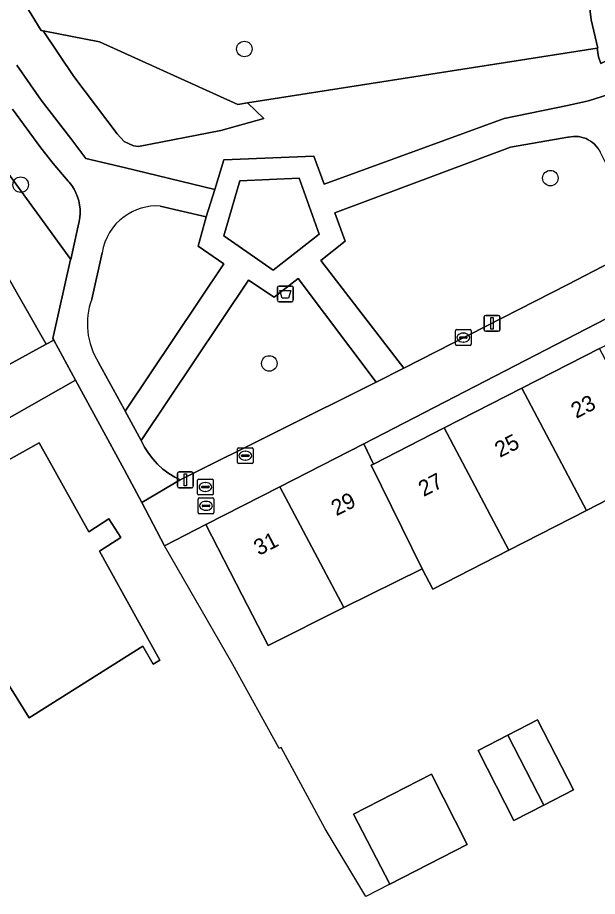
# Model space of a CAD drawing. Extents: x 160377 to 161131, y 383938 to 384853.
# Drawn here: x 160993.3 to 161029.8, y 384084.7 to 384140 of the extents above; entities that cross this region are included whole.
import ezdxf

# ---------------------------------------------------------------- set-up
doc = ezdxf.new("R2010")
doc.units = 0
for name, color, linetype in [('IMGEO_Afvalbak', 7, 'Continuous'), ('IMGEO_Boom', 7, 'Continuous'), ('IMGEO_Brandkraan', 7, 'Continuous'), ('IMGEO_Erf', 7, 'Continuous'), ('IMGEO_Groenvoorziening', 7, 'Continuous'), ('IMGEO_Kolk', 7, 'Continuous'), ('IMGEO_Lichtmast', 7, 'Continuous'), ('IMGEO_Loofbos', 7, 'Continuous'), ('IMGEO_Muur', 7, 'Continuous'), ('IMGEO_Pand', 7, 'Continuous'), ('IMGEO_Pand_nummerreeks', 7, 'Continuous'), ('IMGEO_Rioolput', 7, 'Continuous'), ('IMGEO_Voetpad_halfverhard', 7, 'Continuous'), ('IMGEO_Voetpad_open', 7, 'Continuous')]:
    doc.layers.add(name, color=color, linetype=linetype)

msp = doc.modelspace()

# ---------------------------------------------------------------- linework, layer by layer
at = {"layer": 'IMGEO_Afvalbak'}
for p, q in [((161009.768, 384123.109), (161010.558, 384123.109)), ((161010.558, 384123.109), (161009.768, 384123.109)), ((161009.668, 384122.209), (161009.668, 384123.009)), ((161009.668, 384123.009), (161009.668, 384122.209)), ((161010.658, 384123.009), (161010.658, 384122.209)), ((161010.658, 384122.209), (161010.658, 384123.009)), ((161010.558, 384122.109), (161009.768, 384122.109)), ((161009.768, 384122.109), (161010.558, 384122.109))]:
    msp.add_line(p, q, dxfattribs=at)
msp.add_lwpolyline([(161009.811, 384122.823), (161010.515, 384122.823), (161010.366, 384122.353), (161009.96, 384122.353), (161009.811, 384122.823)], dxfattribs=at)
for centre, start, end in [((161009.768, 384123.009), 90, 180), ((161009.768, 384123.009), 90, 180), ((161010.558, 384123.009), 0, 90), ((161010.558, 384123.009), 360, 90), ((161009.768, 384122.209), 180, 270), ((161009.768, 384122.209), 180, 270), ((161010.558, 384122.209), 270, 0), ((161010.558, 384122.209), 270, 0)]:
    msp.add_arc(centre, 0.1, start, end, dxfattribs=at)
at = {"layer": 'IMGEO_Boom'}
for centre in [(161007.58, 384138.031), (161026.855, 384129.9), (160993.491, 384129.487), (161009.15, 384118.235)]:
    msp.add_circle(centre, 0.489, dxfattribs=at)
at = {"layer": 'IMGEO_Brandkraan'}
for p, q in [((161004.737, 384109.773), (161005.589, 384109.773)), ((161004.662, 384108.847), (161004.662, 384109.699)), ((161004.921, 384109.267), (161004.921, 384109.279)), ((161005.359, 384109.23), (161004.961, 384109.23)), ((161004.964, 384109.316), (161005.362, 384109.316)), ((161005.15, 384109.553), (161005.175, 384109.553)), ((161005.405, 384109.279), (161005.405, 384109.267)), ((161005.663, 384109.699), (161005.663, 384108.847)), ((161005.589, 384108.773), (161004.737, 384108.773)), ((161005.173, 384108.993), (161005.148, 384108.993))]:
    msp.add_line(p, q, dxfattribs=at)
for points in [[(161004.737, 384109.773), (161005.589, 384109.773)], [(161004.662, 384108.847), (161004.662, 384109.699)], [(161005.663, 384109.699), (161005.663, 384108.847)], [(161005.589, 384108.773), (161004.737, 384108.773)]]:
    msp.add_lwpolyline(points, dxfattribs=at)
for centre, radius, start, end in [((161004.739, 384109.697), 0.0765, 91.552, 178.448), ((161004.739, 384109.697), 0.0765, 91.552, 178.448), ((161005.587, 384109.697), 0.0765, 1.552, 88.448), ((161005.587, 384109.697), 0.0765, 1.552, 88.448), ((161004.961, 384109.276), 0.0403, 85.8775, 175.7526), ((161004.958, 384109.266), 0.0366, 178.938, 274.7102), ((161005.362, 384109.273), 0.043, 264.8664, 352.4533), ((161005.366, 384109.278), 0.0386, 1.7309, 96.639), ((161004.739, 384108.849), 0.0765, 181.552, 268.448), ((161004.739, 384108.849), 0.0765, 181.552, 268.448), ((161005.587, 384108.849), 0.0765, 271.552, 358.448), ((161005.587, 384108.849), 0.0765, 271.552, 358.448)]:
    msp.add_arc(centre, radius, start, end, dxfattribs=at)
for centre, major_axis, ratio, start_param, end_param in [((161005.149, 384109.273), (-0.387, 0.002), 0.722429, 4.712389, 7.853982), ((161005.174, 384109.273), (-0.39, 0.002), 0.717154, 1.570796, 4.712389)]:
    msp.add_ellipse(centre, major_axis=major_axis, ratio=ratio, start_param=start_param, end_param=end_param, dxfattribs=at)
at = {"layer": 'IMGEO_Erf'}
for points in [[(160985.026, 384113.922), (160995.093, 384119.446), (160961.359, 384178.569)], [(161053.635, 384084.865), (161050.608, 384090.89), (161045.881, 384100.391), (161043.612, 384104.8), (161038.91, 384114.001), (161034.462, 384111.719), (161034.018, 384111.491), (161029.137, 384108.987), (161024.243, 384106.476), (161019.449, 384104.017), (161018.79, 384105.301), (161013.842, 384102.878), (161009.074, 384100.476), (161007.442, 384103.643), (161005.151, 384108.087), (161002.558, 384106.761), (161001.122, 384109.491), (161000, 384111.558), (160996.945, 384117.185), (160973.277, 384103.758), (160955.415, 384093.563), (160973.352, 384063.337)]]:
    msp.add_lwpolyline(points, dxfattribs=at)
for points in [[(161034.221, 384123.045), (161015.1, 384113.176), (161015.705, 384111.888), (161020.168, 384114.173), (161025.064, 384116.68), (161029.948, 384119.18), (161034.932, 384121.732)], [(160998.448, 384106.427), (161002.265, 384099.56), (161001.827, 384099.309), (161001.18, 384100.437), (160994.027, 384095.922), (160986.399, 384108.157), (160984.822, 384107.291), (160984.627, 384107.638), (160994.647, 384113.236), (160997.78, 384107.634), (160999.052, 384108.453), (160999.794, 384107.273)], [(161024.169, 384094.835), (161026.038, 384095.793), (161028.32, 384091.394), (161026.451, 384090.436), (161024.56, 384089.467), (161022.3, 384093.877)], [(161016.744, 384085.463), (161014.454, 384089.856), (161019.363, 384092.372), (161021.619, 384087.961)]]:
    msp.add_lwpolyline(points, close=True, dxfattribs=at)
at = {"layer": 'IMGEO_Groenvoorziening'}
for points in [[(160990.804, 384145.659), (160994.784, 384139.197), (160994.905, 384139.173), (160998.463, 384138.478), (161007.166, 384134.542), (161007.773, 384134.636), (161029.797, 384138.079), (161029.845, 384138.087), (161029.42, 384139.864), (161026.658, 384162.899), (161031.19, 384164.897), (161032.918, 384165.659), (161032.625, 384166.23), (161024.34, 384182.407)], [(161026.658, 384162.899), (161029.42, 384139.864), (161029.845, 384138.087), (161029.797, 384138.079), (161029.891, 384137.526), (161030.032, 384137.124), (161035.775, 384140.036)], [(161035.775, 384140.036), (161030.032, 384137.124), (161029.891, 384137.526), (161029.797, 384138.079), (161007.773, 384134.636), (161008.817, 384133.644), (161006.091, 384132.899), (161000.909, 384131.883), (161000.593, 384131.93), (161000.006, 384132.205), (160999.577, 384132.69), (160996.839, 384136.297), (160994.905, 384139.173), (160994.784, 384139.197), (160990.804, 384145.659)], [(160993.254, 384137.015), (160994.774, 384134.801), (160996.642, 384132.385), (160997.603, 384131.137), (161000, 384130.562), (161005.718, 384129.189), (161006.277, 384131.058), (161011.953, 384131.288), (161012.616, 384129.509), (161018.887, 384131.803), (161023.951, 384133.656), (161027.944, 384134.478), (161029.247, 384134.766), (161030.518, 384135.17), (161031.749, 384135.685), (161031.909, 384135.762), (161033.725, 384136.709), (161040.371, 384140.079)], [(160998.396, 384118.295), (161000, 384115.366), (161000.069, 384115.24), (161006.284, 384124.497), (161004.667, 384125.626), (161005.166, 384127.453), (161002.284, 384128.143)], [(160998.629, 384125.205), (160997.966, 384122.291)]]:
    msp.add_lwpolyline(points, dxfattribs=at)
for points in [[(161008.817, 384133.644), (161007.773, 384134.636), (161007.166, 384134.542), (160998.463, 384138.478), (160994.905, 384139.173), (160996.839, 384136.297), (160999.577, 384132.69), (161000.006, 384132.205), (161000.593, 384131.93), (161000.909, 384131.883), (161006.091, 384132.899)], [(161017.635, 384117.933), (161027.949, 384123.209), (161032.896, 384125.768), (161030.017, 384131.52), (161029.94, 384131.661), (161029.85, 384131.795), (161029.748, 384131.92), (161029.636, 384132.036), (161029.514, 384132.141), (161029.383, 384132.235), (161029.245, 384132.317), (161029.099, 384132.386), (161028.948, 384132.441), (161028.792, 384132.483), (161028.634, 384132.511), (161028.473, 384132.525), (161028.312, 384132.525), (161028.152, 384132.509), (161027.993, 384132.48), (161027.956, 384132.471), (161024.349, 384131.847), (161013.27, 384127.709), (161013.929, 384125.926), (161012.392, 384124.721)], [(161003.527, 384110.903), (161015.881, 384117.064), (161010.964, 384123.59), (161009.453, 384122.412), (161007.837, 384123.468), (161001.084, 384113.378), (161001.291, 384112.974), (161001.534, 384112.59), (161001.81, 384112.229), (161002.117, 384111.895), (161002.453, 384111.589), (161002.815, 384111.314), (161003.2, 384111.073)]]:
    msp.add_lwpolyline(points, close=True, dxfattribs=at)
for centre, radius, start, end in [((161002.066, 384124.669), 3.48, 86.4148, 126.4213), ((161002.061, 384124.675), 3.473, 126.4051, 171.222), ((161002.251, 384120.731), 4.56, 159.9931, 212.2906)]:
    msp.add_arc(centre, radius, start, end, dxfattribs=at)
at = {"layer": 'IMGEO_Kolk'}
for p, q in [((161020.87, 384119.438), (161020.87, 384120.29)), ((161020.945, 384120.364), (161021.797, 384120.364)), ((161021.871, 384120.29), (161021.871, 384119.438)), ((161021.129, 384119.858), (161021.129, 384119.87)), ((161021.567, 384119.821), (161021.169, 384119.821)), ((161021.172, 384119.907), (161021.57, 384119.907)), ((161021.358, 384120.144), (161021.383, 384120.144)), ((161021.613, 384119.87), (161021.613, 384119.858)), ((161021.797, 384119.364), (161020.945, 384119.364)), ((161021.381, 384119.584), (161021.356, 384119.584)), ((161007.141, 384112.003), (161007.141, 384112.855)), ((161007.216, 384112.929), (161008.068, 384112.929)), ((161007.629, 384112.709), (161007.654, 384112.709)), ((161008.142, 384112.855), (161008.142, 384112.003)), ((161007.4, 384112.423), (161007.4, 384112.435)), ((161007.838, 384112.386), (161007.44, 384112.386)), ((161007.443, 384112.472), (161007.841, 384112.472)), ((161007.652, 384112.149), (161007.627, 384112.149)), ((161007.884, 384112.435), (161007.884, 384112.423)), ((161008.068, 384111.929), (161007.216, 384111.929))]:
    msp.add_line(p, q, dxfattribs=at)
for points in [[(161020.87, 384119.438), (161020.87, 384120.29)], [(161020.945, 384120.364), (161021.797, 384120.364)], [(161021.871, 384120.29), (161021.871, 384119.438)], [(161021.797, 384119.364), (161020.945, 384119.364)], [(161007.141, 384112.003), (161007.141, 384112.855)], [(161007.216, 384112.929), (161008.068, 384112.929)], [(161008.142, 384112.855), (161008.142, 384112.003)], [(161008.068, 384111.929), (161007.216, 384111.929)]]:
    msp.add_lwpolyline(points, dxfattribs=at)
for centre, radius, start, end in [((161020.947, 384120.288), 0.0765, 91.552, 178.448), ((161020.947, 384120.288), 0.0765, 91.552, 178.448), ((161021.795, 384120.288), 0.0765, 1.552, 88.448), ((161021.795, 384120.288), 0.0765, 1.552, 88.448), ((161021.169, 384119.867), 0.0403, 85.8775, 175.7526), ((161021.166, 384119.857), 0.0366, 178.938, 274.7102), ((161021.57, 384119.864), 0.043, 264.8664, 352.4533), ((161021.574, 384119.869), 0.0386, 1.7309, 96.639), ((161020.947, 384119.44), 0.0765, 181.552, 268.448), ((161020.947, 384119.44), 0.0765, 181.552, 268.448), ((161021.795, 384119.44), 0.0765, 271.552, 358.448), ((161021.795, 384119.44), 0.0765, 271.552, 358.448), ((161007.218, 384112.853), 0.0765, 91.552, 178.448), ((161007.218, 384112.853), 0.0765, 91.552, 178.448), ((161008.066, 384112.853), 0.0765, 1.552, 88.448), ((161008.066, 384112.853), 0.0765, 1.552, 88.448), ((161007.218, 384112.005), 0.0765, 181.552, 268.448), ((161007.218, 384112.005), 0.0765, 181.552, 268.448), ((161007.44, 384112.432), 0.0403, 85.8775, 175.7526), ((161007.437, 384112.422), 0.0366, 178.938, 274.7102), ((161007.841, 384112.429), 0.043, 264.8664, 352.4533), ((161007.845, 384112.434), 0.0386, 1.7309, 96.639), ((161008.066, 384112.005), 0.0765, 271.552, 358.448), ((161008.066, 384112.005), 0.0765, 271.552, 358.448)]:
    msp.add_arc(centre, radius, start, end, dxfattribs=at)
for centre, major_axis, ratio, start_param, end_param in [((161021.357, 384119.864), (-0.387, 0.002), 0.722429, 4.712389, 7.853982), ((161021.382, 384119.864), (-0.39, 0.002), 0.717154, 1.570796, 4.712389), ((161007.628, 384112.429), (-0.387, 0.002), 0.722429, 4.712389, 7.853982), ((161007.653, 384112.429), (-0.39, 0.002), 0.717154, 1.570796, 4.712389)]:
    msp.add_ellipse(centre, major_axis=major_axis, ratio=ratio, start_param=start_param, end_param=end_param, dxfattribs=at)
at = {"layer": 'IMGEO_Lichtmast'}
for p, q in [((161022.682, 384120.36), (161022.682, 384121.16)), ((161022.682, 384121.16), (161022.682, 384120.36)), ((161022.782, 384121.26), (161023.572, 384121.26)), ((161023.572, 384121.26), (161022.782, 384121.26)), ((161023.672, 384121.16), (161023.672, 384120.36)), ((161023.672, 384120.36), (161023.672, 384121.16)), ((161023.572, 384120.26), (161022.782, 384120.26)), ((161022.782, 384120.26), (161023.572, 384120.26)), ((161003.465, 384111.406), (161004.255, 384111.406)), ((161004.255, 384111.406), (161003.465, 384111.406)), ((161003.365, 384110.506), (161003.365, 384111.306)), ((161003.365, 384111.306), (161003.365, 384110.506)), ((161004.355, 384111.306), (161004.355, 384110.506)), ((161004.355, 384110.506), (161004.355, 384111.306)), ((161004.255, 384110.406), (161003.465, 384110.406)), ((161003.465, 384110.406), (161004.255, 384110.406))]:
    msp.add_line(p, q, dxfattribs=at)
for points in [[(161023.102, 384121.135), (161023.252, 384121.135), (161023.252, 384120.385), (161023.102, 384120.385), (161023.102, 384121.135)], [(161003.785, 384111.281), (161003.935, 384111.281), (161003.935, 384110.531), (161003.785, 384110.531), (161003.785, 384111.281)]]:
    msp.add_lwpolyline(points, dxfattribs=at)
for centre, start, end in [((161022.782, 384121.16), 90, 180), ((161022.782, 384121.16), 90, 180), ((161023.572, 384121.16), 0, 90), ((161023.572, 384121.16), 360, 90), ((161022.782, 384120.36), 180, 270), ((161022.782, 384120.36), 180, 270), ((161023.572, 384120.36), 270, 0), ((161023.572, 384120.36), 270, 0), ((161003.465, 384111.306), 90, 180), ((161003.465, 384111.306), 90, 180), ((161004.255, 384111.306), 0, 90), ((161004.255, 384111.306), 360, 90), ((161003.465, 384110.506), 180, 270), ((161003.465, 384110.506), 180, 270), ((161004.255, 384110.506), 270, 0), ((161004.255, 384110.506), 270, 0)]:
    msp.add_arc(centre, 0.1, start, end, dxfattribs=at)
at = {"layer": 'IMGEO_Loofbos'}
msp.add_lwpolyline([(160966.147, 384183.255), (160964.906, 384181.911), (160961.359, 384178.569), (160995.093, 384119.446), (160995.582, 384119.696), (160995.52, 384119.81), (160996.64, 384124.77), (160996.642, 384124.777), (160991.54, 384131.77), (160987.179, 384139.766), (160982.252, 384148.488), (160975.306, 384162.057)], close=True, dxfattribs=at)
msp.add_lwpolyline([(160991.54, 384131.77), (160996.642, 384124.777), (160997.122, 384126.903), (160997.185, 384127.16), (160997.225, 384127.422), (160997.242, 384127.687), (160997.234, 384127.951), (160997.204, 384128.214), (160997.149, 384128.474), (160997.072, 384128.727), (160996.973, 384128.973), (160996.851, 384129.208), (160996.71, 384129.432), (160996.549, 384129.642), (160996.485, 384129.716), (160995.536, 384130.813), (160994.769, 384131.803), (160992.979, 384134.231)], dxfattribs=at)
at = {"layer": 'IMGEO_Muur'}
for points in [[(161002.558, 384106.761), (161005.151, 384108.087)], [(161015.229, 384084.687), (161012.666, 384088.946), (161009.894, 384094.062), (161009.767, 384094.003), (161006.849, 384099.293), (161002.558, 384106.761)], [(161016.744, 384085.463), (161015.229, 384084.687)]]:
    msp.add_lwpolyline(points, dxfattribs=at)
at = {"layer": 'IMGEO_Pand'}
for points in [[(161034.018, 384111.491), (161029.948, 384119.18), (161025.064, 384116.68), (161029.137, 384108.987)], [(161020.168, 384114.173), (161024.243, 384106.476), (161029.137, 384108.987), (161025.064, 384116.68)], [(161020.168, 384114.173), (161015.705, 384111.888), (161015.575, 384111.824), (161018.79, 384105.301), (161019.449, 384104.017), (161024.243, 384106.476)], [(160998.448, 384106.427), (160999.794, 384107.273), (160999.052, 384108.453), (160997.78, 384107.634), (160994.647, 384113.236), (160984.627, 384107.638), (160984.822, 384107.291), (160986.399, 384108.157), (160994.027, 384095.922), (161001.18, 384100.437), (161001.827, 384099.309), (161002.265, 384099.56)], [(161013.842, 384102.878), (161018.79, 384105.301), (161015.575, 384111.824), (161015.705, 384111.888), (161015.1, 384113.176), (161009.82, 384110.475)], [(161013.842, 384102.878), (161009.82, 384110.475), (161005.151, 384108.087), (161007.442, 384103.643), (161009.074, 384100.476)], [(161024.169, 384094.835), (161026.451, 384090.436), (161028.32, 384091.394), (161026.038, 384095.793)], [(161024.169, 384094.835), (161022.3, 384093.877), (161024.56, 384089.467), (161026.451, 384090.436)], [(161019.363, 384092.372), (161014.454, 384089.856), (161016.744, 384085.463), (161021.619, 384087.961)]]:
    msp.add_lwpolyline(points, close=True, dxfattribs=at)
at = {"layer": 'IMGEO_Rioolput'}
for p, q in [((161004.625, 384110.032), (161004.625, 384110.884)), ((161004.7, 384110.958), (161005.552, 384110.958)), ((161005.626, 384110.884), (161005.626, 384110.032)), ((161004.884, 384110.452), (161004.884, 384110.464)), ((161005.322, 384110.415), (161004.924, 384110.415)), ((161004.927, 384110.501), (161005.325, 384110.501)), ((161005.113, 384110.738), (161005.138, 384110.738)), ((161005.368, 384110.464), (161005.368, 384110.452)), ((161005.552, 384109.958), (161004.7, 384109.958)), ((161005.136, 384110.178), (161005.111, 384110.178))]:
    msp.add_line(p, q, dxfattribs=at)
for points in [[(161004.625, 384110.032), (161004.625, 384110.884)], [(161004.7, 384110.958), (161005.552, 384110.958)], [(161005.626, 384110.884), (161005.626, 384110.032)], [(161005.552, 384109.958), (161004.7, 384109.958)]]:
    msp.add_lwpolyline(points, dxfattribs=at)
for centre, radius, start, end in [((161004.702, 384110.882), 0.0765, 91.552, 178.448), ((161004.702, 384110.882), 0.0765, 91.552, 178.448), ((161005.55, 384110.882), 0.0765, 1.552, 88.448), ((161005.55, 384110.882), 0.0765, 1.552, 88.448), ((161004.924, 384110.461), 0.0403, 85.8775, 175.7526), ((161004.921, 384110.451), 0.0366, 178.938, 274.7102), ((161005.325, 384110.458), 0.043, 264.8664, 352.4533), ((161005.329, 384110.463), 0.0386, 1.7309, 96.639), ((161004.702, 384110.034), 0.0765, 181.552, 268.448), ((161004.702, 384110.034), 0.0765, 181.552, 268.448), ((161005.55, 384110.034), 0.0765, 271.552, 358.448), ((161005.55, 384110.034), 0.0765, 271.552, 358.448)]:
    msp.add_arc(centre, radius, start, end, dxfattribs=at)
for centre, major_axis, ratio, start_param, end_param in [((161005.112, 384110.458), (-0.387, 0.002), 0.722429, 4.712389, 7.853982), ((161005.137, 384110.458), (-0.39, 0.002), 0.717154, 1.570796, 4.712389)]:
    msp.add_ellipse(centre, major_axis=major_axis, ratio=ratio, start_param=start_param, end_param=end_param, dxfattribs=at)
at = {"layer": 'IMGEO_Voetpad_halfverhard'}
for points in [[(161002.284, 384128.143), (161005.166, 384127.453), (161005.718, 384129.189), (161000, 384130.562), (160997.603, 384131.137), (160996.642, 384132.385), (160994.774, 384134.801), (160993.254, 384137.015)], [(161030.518, 384135.17), (161029.247, 384134.766), (161027.944, 384134.478), (161023.951, 384133.656), (161018.887, 384131.803), (161012.616, 384129.509), (161011.953, 384131.288), (161006.277, 384131.058), (161005.718, 384129.189), (161005.166, 384127.453), (161004.667, 384125.626), (161006.284, 384124.497), (161000.069, 384115.24), (161001.084, 384113.378), (161007.837, 384123.468), (161009.453, 384122.412), (161010.964, 384123.59), (161015.881, 384117.064), (161017.635, 384117.933), (161012.392, 384124.721), (161013.929, 384125.926), (161013.27, 384127.709), (161024.349, 384131.847), (161027.956, 384132.471), (161027.993, 384132.48), (161028.152, 384132.509), (161028.312, 384132.525), (161028.473, 384132.525), (161028.634, 384132.511), (161028.792, 384132.483), (161028.948, 384132.441), (161029.099, 384132.386), (161029.245, 384132.317), (161029.383, 384132.235), (161029.514, 384132.141), (161029.636, 384132.036), (161029.748, 384131.92), (161029.85, 384131.795)], [(160992.979, 384134.231), (160994.769, 384131.803), (160995.536, 384130.813), (160996.485, 384129.716), (160996.549, 384129.642), (160996.71, 384129.432), (160996.851, 384129.208), (160996.973, 384128.973), (160997.072, 384128.727), (160997.149, 384128.474), (160997.204, 384128.214), (160997.234, 384127.951), (160997.242, 384127.687), (160997.225, 384127.422), (160997.185, 384127.16), (160997.122, 384126.903), (160996.642, 384124.777), (160996.64, 384124.77), (160995.52, 384119.81), (160995.582, 384119.696), (160996.945, 384117.185), (161000, 384111.558), (161001.122, 384109.491), (161003.527, 384110.903), (161003.2, 384111.073), (161002.815, 384111.314), (161002.453, 384111.589), (161002.117, 384111.895), (161001.81, 384112.229), (161001.534, 384112.59), (161001.291, 384112.974), (161001.084, 384113.378), (161000.069, 384115.24), (161000, 384115.366), (160998.396, 384118.295)], [(160997.966, 384122.291), (160998.629, 384125.205)]]:
    msp.add_lwpolyline(points, dxfattribs=at)
msp.add_lwpolyline([(161009.39, 384124.097), (161006.288, 384126.258), (161007.289, 384129.734), (161011.04, 384129.887), (161012.286, 384126.382)], close=True, dxfattribs=at)
for centre, radius, start, end in [((161002.066, 384124.669), 3.48, 86.4148, 126.4213), ((161002.061, 384124.675), 3.473, 126.4051, 171.222), ((161002.251, 384120.731), 4.56, 159.9931, 212.2906)]:
    msp.add_arc(centre, radius, start, end, dxfattribs=at)
at = {"layer": 'IMGEO_Voetpad_open'}
msp.add_lwpolyline([(161046.535, 384132.75), (161035.555, 384127.128), (161032.896, 384125.768), (161027.949, 384123.209), (161017.635, 384117.933), (161015.881, 384117.064), (161003.527, 384110.903), (161001.122, 384109.491), (161002.558, 384106.761), (161005.151, 384108.087), (161009.82, 384110.475), (161015.1, 384113.176), (161034.221, 384123.045), (161036.946, 384124.434), (161050.415, 384131.358)], dxfattribs=at)
for points in [[(161009.39, 384124.097), (161012.286, 384126.382), (161011.04, 384129.887), (161007.289, 384129.734), (161006.288, 384126.258)], [(160955.415, 384093.563), (160973.277, 384103.758), (160996.945, 384117.185), (160995.582, 384119.696), (160995.093, 384119.446), (160985.026, 384113.922), (160968.67, 384104.572), (160958.287, 384098.637), (160953.893, 384096.124)]]:
    msp.add_lwpolyline(points, close=True, dxfattribs=at)

# ---------------------------------------------------------------- texts
at = {"layer": 'IMGEO_Pand_nummerreeks'}
for s, rotation, p in [('23', 27.1119, (161028.481, 384114.744)), ('25', 27.1119, (161023.675, 384112.283)), ('27', 27.1119, (161018.868, 384109.822)), ('29', 27.0901, (161013.37, 384108.607)), ('31', 27.0901, (161008.497, 384106.114))]:
    msp.add_text(s, height=1, rotation=rotation, dxfattribs=at).set_placement(p)

doc.saveas('drawing.dxf')
